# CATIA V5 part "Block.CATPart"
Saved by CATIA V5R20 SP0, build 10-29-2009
Part number: Block
Material "Steel": density 7860 kg/m3, Young's modulus 2e+11 Pa, Poisson ratio 0.266, thermal expansion 1.17e-05 1/K
Bounding box of the stored display mesh (mm): x -70 to 0, y -70 to 70, z -40 to 195
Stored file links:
  E:\Ehsan\Amoozesh\CATIA\CATIA Course\Basic\Exercises\Assembly\12\Block.CATPart
  D:\CATIA V5R20\B20\intel_a\startup\materials\Catalog.CATMaterial
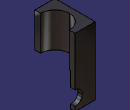
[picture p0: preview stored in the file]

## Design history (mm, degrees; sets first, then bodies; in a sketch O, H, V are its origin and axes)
Body1 (main body), material "Steel"
  Sketch1 on yz-plane, origin (0, 0, 0), H (0, 1, 0), V (0, 0, 1)
    line L1 (55, -40) -> (70, -40)
    line L2 (70, -40) -> (70, 195)
    line L3 (70, 195) -> (-70, 195)
    line L4 (-70, 195) -> (-70, 75)
    line L5 (-70, 75) -> (55, 75)
    line L6 (55, 75) -> (55, -40)
  Pad1: profile Sketch1, direction (-1, 0, 0), length 70
  Sketch2 on xy-plane, origin (0, 0, 0), H (1, 0, 0), V (0, 1, 0)
    circle A1 centre (0, 0) radius 50
  Pocket1: profile Sketch2, direction (0, 0, -1), through (limit type 3)
  Sketch3 on zx-plane, origin (0, 0, 0), H (-1, 0, 0), V (0, 0, 1)
    circle A1 centre (0, 0) radius 25
  Pocket2: profile Sketch3, direction (0, -1, 0), through (limit type 3)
